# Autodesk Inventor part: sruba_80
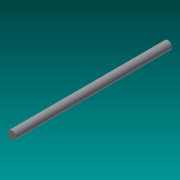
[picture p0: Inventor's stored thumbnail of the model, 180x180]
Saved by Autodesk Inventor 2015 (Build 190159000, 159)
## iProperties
Created: 2016-02
Part Number: sruba_80
Material: Generic
Document SubType Name: Modeling
Designer: Rafał
Density: 1 g/cm^3
Appearance: Default
Author: Rafał
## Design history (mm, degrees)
sketch "Sketch1"
  geometry: C1 r 4 at (0, 0); 1 further point
  constraints: 1 centre point, 1 coincident
  dimensions: "d0" = 8 diameter of C1
extrude "Extrusion1" new body sketch "Sketch1" distance "d1" = 150; taper "d2" = 0 deg
body "Solid1"
